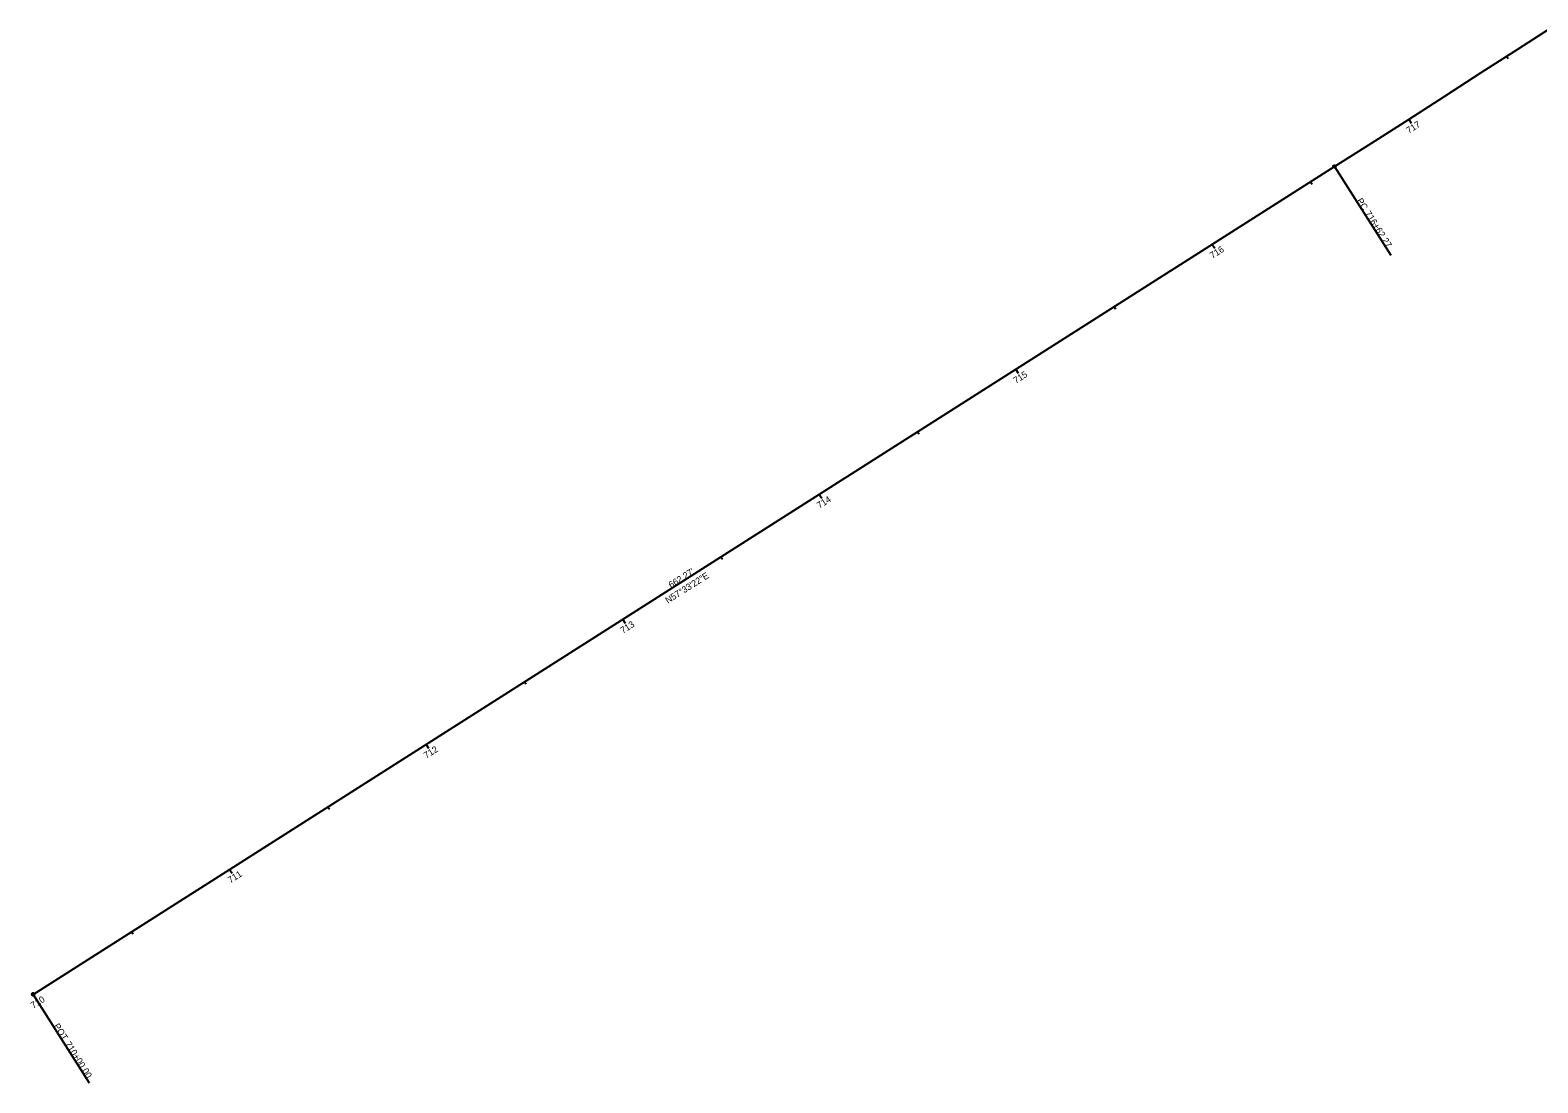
# Model space of a CAD drawing. Extents: x 1492452 to 1496782, y 514026 to 517659.
# Drawn here: x 1492452 to 1493100, y 514026 to 514478 of the extents above; entities that cross this region are included whole.
import ezdxf

# ---------------------------------------------------------------- set-up
doc = ezdxf.new("R2010")
doc.units = 0
for name, color, linetype in [('Default', 7, 'Continuous'), ('DR_X_Ditch', 7, 'Continuous'), ('DT_X_Break_Line', 7, 'Continuous'), ('DT_X_TIN_Hull', 7, 'Continuous'), ('DT_X_Void', 7, 'Continuous'), ('GE_X_Cells', 7, 'Continuous'), ('RD_X_Cells', 7, 'Continuous'), ('RD_X_GR_Lt', 7, 'Continuous'), ('SV_X_Random_Point', 7, 'Continuous'), ('UT_X_Electric_Cells', 7, 'Continuous'), ('UT_X_Misc_Cells', 7, 'Continuous'), ('UT_X_Water', 7, 'Continuous'), ('UT_X_Water_Cells', 7, 'Continuous'), ('VG_X_Cells', 7, 'Continuous')]:
    doc.layers.add(name, color=color, linetype=linetype)

msp = doc.modelspace()

# ---------------------------------------------------------------- linework, layer by layer
at = {"layer": 'Default'}
msp.add_line((1492453.68, 514063.81), (1493012.58, 514419.1), dxfattribs=at)
msp.add_arc((1486425.91, 524780.42), 12277.67, 302.444021, 313.600151, dxfattribs=at)
at = {"layer": 'DT_X_TIN_Hull'}
for p, q in [((1493086.44, 514466.43), (1493087.09, 514465.42)), ((1493044.39, 514439.39), (1493045.46, 514437.7)), ((1493002.22, 514412.51), (1493002.86, 514411.5)), ((1492960.02, 514385.69), (1492961.1, 514384)), ((1492917.83, 514358.87), (1492918.47, 514357.85)), ((1492875.63, 514332.04), (1492876.71, 514330.35)), ((1492833.44, 514305.22), (1492834.08, 514304.21)), ((1492791.24, 514278.4), (1492792.31, 514276.71)), ((1492749.05, 514251.57), (1492749.69, 514250.56)), ((1492706.85, 514224.75), (1492707.92, 514223.06)), ((1492664.65, 514197.92), (1492665.3, 514196.91)), ((1492622.46, 514171.1), (1492623.53, 514169.41)), ((1492580.26, 514144.28), (1492580.91, 514143.26)), ((1492538.07, 514117.45), (1492539.14, 514115.76)), ((1492495.87, 514090.63), (1492496.51, 514089.62)), ((1492453.68, 514063.81), (1492454.75, 514062.12))]:
    msp.add_line(p, q, dxfattribs=at)
at = {"layer": 'DT_X_Void'}
for p, q in [((1493012.58, 514419.1), (1493036.72, 514381.12)), ((1492453.68, 514063.81), (1492477.82, 514025.83))]:
    msp.add_line(p, q, dxfattribs=at)
for centre in [(1493012.58, 514419.1), (1492453.68, 514063.81)]:
    msp.add_circle(centre, 0.6, dxfattribs=at)
at = {"layer": 'GE_X_Cells'}
msp.add_line((1492453.68, 514063.81), (1493012.58, 514419.1), dxfattribs=at)
msp.add_arc((1486425.91, 524780.42), 12277.67, 302.444021, 313.600151, dxfattribs=at)
at = {"layer": 'RD_X_Cells'}
for p, q in [((1493012.58, 514419.1), (1493036.72, 514381.12)), ((1492453.68, 514063.81), (1492477.82, 514025.83))]:
    msp.add_line(p, q, dxfattribs=at)
for centre in [(1493012.58, 514419.1), (1492453.68, 514063.81)]:
    msp.add_circle(centre, 0.6, dxfattribs=at)
at = {"layer": 'UT_X_Misc_Cells'}
for p, q in [((1493012.58, 514419.1), (1493036.72, 514381.12)), ((1492453.68, 514063.81), (1492477.82, 514025.83))]:
    msp.add_line(p, q, dxfattribs=at)
for centre in [(1493012.58, 514419.1), (1492453.68, 514063.81)]:
    msp.add_circle(centre, 0.6, dxfattribs=at)
at = {"layer": 'UT_X_Water_Cells'}
for p, q in [((1493044.39, 514439.39), (1493045.03, 514438.38)), ((1492960.02, 514385.69), (1492960.67, 514384.68)), ((1492875.63, 514332.04), (1492876.71, 514330.35)), ((1492791.24, 514278.4), (1492791.89, 514277.38)), ((1492706.85, 514224.75), (1492707.49, 514223.74)), ((1492622.46, 514171.1), (1492623.1, 514170.09)), ((1492538.07, 514117.45), (1492538.71, 514116.44)), ((1492453.68, 514063.81), (1492454.75, 514062.12))]:
    msp.add_line(p, q, dxfattribs=at)
at = {"layer": 'VG_X_Cells'}
for p, q in [((1492875.63, 514332.04), (1492876.28, 514331.03)), ((1492453.68, 514063.81), (1492454.75, 514062.12))]:
    msp.add_line(p, q, dxfattribs=at)

# ---------------------------------------------------------------- texts
at = {"layer": 'DR_X_Ditch'}
msp.add_text("662.27'", height=2.8, rotation=32.44402, dxfattribs=at).set_placement((1492727.63, 514238.01))
at = {"layer": 'DT_X_Break_Line'}
msp.add_text('N57°33\'22"E', height=2.8, rotation=32.44402, dxfattribs=at).set_placement((1492726.26, 514231.4))
at = {"layer": 'DT_X_TIN_Hull'}
for s, rotation, p in [('717', 32.62009, (1493044.43, 514433.12)), ('716', 32.44402, (1492960.1, 514379.46)), ('715', 32.44402, (1492875.7, 514325.8)), ('714', 32.44402, (1492791.35, 514272.19)), ('713', 32.44402, (1492706.94, 514218.52)), ('712', 32.44402, (1492622.54, 514164.87)), ('711', 32.44402, (1492538.41, 514111.39)), ('710', 32.44402, (1492453.75, 514057.57))]:
    msp.add_text(s, height=2.8, rotation=rotation, dxfattribs=at).set_placement(p)
at = {"layer": 'DT_X_Void'}
for s, p in [('PC', (1493021.93, 514404.47)), ('716+62.27', (1493025.43, 514398.96)), ('POT', (1492462.36, 514050.23)), ('710+00.00', (1492467.26, 514042.52))]:
    msp.add_text(s, height=2.8, rotation=302.44402, dxfattribs=at).set_placement(p)
at = {"layer": 'RD_X_Cells'}
for s, p in [('PC', (1493021.93, 514404.47)), ('716+62.27', (1493025.43, 514398.96)), ('POT', (1492462.36, 514050.23)), ('710+00.00', (1492467.26, 514042.52))]:
    msp.add_text(s, height=2.8, rotation=302.44402, dxfattribs=at).set_placement(p)
at = {"layer": 'RD_X_GR_Lt'}
msp.add_text("662.27'", height=2.8, rotation=32.44402, dxfattribs=at).set_placement((1492727.63, 514238.01))
at = {"layer": 'SV_X_Random_Point'}
msp.add_text('N57°33\'22"E', height=2.8, rotation=32.44402, dxfattribs=at).set_placement((1492726.26, 514231.4))
at = {"layer": 'UT_X_Electric_Cells'}
msp.add_text('N57°33\'22"E', height=2.8, rotation=32.44402, dxfattribs=at).set_placement((1492726.26, 514231.4))
at = {"layer": 'UT_X_Misc_Cells'}
for s, p in [('PC', (1493021.93, 514404.47)), ('716+62.27', (1493025.43, 514398.96)), ('POT', (1492462.36, 514050.23)), ('710+00.00', (1492467.26, 514042.52))]:
    msp.add_text(s, height=2.8, rotation=302.44402, dxfattribs=at).set_placement(p)
at = {"layer": 'UT_X_Water'}
msp.add_text("662.27'", height=2.8, rotation=32.44402, dxfattribs=at).set_placement((1492727.63, 514238.01))
at = {"layer": 'UT_X_Water_Cells'}
for s, p in [('715', (1492875.7, 514325.8)), ('710', (1492453.75, 514057.57))]:
    msp.add_text(s, height=2.8, rotation=32.44402, dxfattribs=at).set_placement(p)
at = {"layer": 'VG_X_Cells'}
msp.add_text('710', height=2.8, rotation=32.44402, dxfattribs=at).set_placement((1492453.75, 514057.57))

doc.saveas('drawing.dxf')
